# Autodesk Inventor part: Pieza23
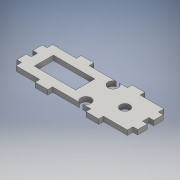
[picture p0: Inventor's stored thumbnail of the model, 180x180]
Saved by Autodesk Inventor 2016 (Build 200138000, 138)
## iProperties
Created: 2016-06
Part Number: Pieza23
Material: Genérico
Document SubType Name: Modeling
Designer: adm
Density: 1 g/cm^3
Appearance: Valor por defecto
Author: adm
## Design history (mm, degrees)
sketch "Boceto1"
  geometry: L1 (-15, -11.5)-(-15, -14.5); L2 (-23, -11.5)-(-23, -14.5); L3 (-23, -14.5)-(-15, -14.5); L4 (-15, -11.5)-(-23, -11.5); L5 (-23, 11.5)-(-15, 11.5); L6 (-15, 14.5)-(-23, 14.5); L7 (-15, 14.5)-(-15, 11.5); L8 (-40, -16.5)-(-40, 16.5); L9 (-35, -9.5)-(-35, -3.5); L10 (-35, 3.5)-(-35, 9.5); L11 (-23, 14.5)-(-23, 11.5); L12 (35, -3.5)-(35, -9.5); L13 (35, 9.5)-(35, 3.5); L14 (35, -9.5)-(38, -9.5); L15 (38, -9.5)-(38, -3.5); L16 (35, -3.5)-(38, -3.5); L17 (35, 9.5)-(38, 9.5); L18 (38, 3.5)-(38, 9.5); L19 (35, 3.5)-(38, 3.5); L20 (-38, 9.5)-(-35, 9.5); L21 (-38, 9.5)-(-38, 3.5); L22 (-38, 3.5)-(-35, 3.5); L23 (-38, -3.5)-(-35, -3.5); L24 (-38, -3.5)-(-38, -9.5); L25 (-38, -9.5)-(-35, -9.5); L26 (35, -11.5)-(-35, 11.5); L27 (-35, -11.5)-(28.913, 9.5); L28 (-40, 16.5)-(40, 16.5); L29 (40, -16.5)-(-40, -16.5); L30 (15, -11.5)-(15, -14.5); L31 (15, 14.5)-(15, 11.5); L32 (15, 11.5)-(23, 11.5); L33 (23, 14.5)-(23, 11.5); L34 (23, 14.5)-(15, 14.5); L35 (23, -11.5)-(23, -14.5); L36 (15, -14.5)-(23, -14.5); L37 (40, 16.5)-(40, -16.5); L38 (23, -11.5)-(15, -11.5); L39 (-35, -11.5)-(35, -11.5); L40 (35, -11.5)-(35, 11.5); L41 (35, 11.5)-(-35, 11.5); L42 (-35, 11.5)-(-35, -11.5); L43 (-35, -11.5)-(35, 11.5); L44 (35, -11.5)-(-35, 11.5); 2 further points
  constraints: 88 end point, 20 parallel, 11 horizontal, 10 perpendicular, 8 vertical, 3 midpoint, 2 horizontal alignment, 1 point on line
  dimensions: "d0" = 70 distance of L26.start L27.start; "d1" = 6 distance of L10.start L10.end; "d2" = 7 distance between parallel lines of L28 L20; "d3" = 6 distance of L18.start L17.end; "d4" = 33 distance between parallel lines of L29 L28; "d5" = 7 distance between parallel lines of L22 L23; "d6" = 7 distance between parallel lines of L29 L25
extrude "Extrusión1" new body sketch "Boceto1" distance "d7" = 3; taper "d8" = 0 deg
sketch "Boceto2"
  geometry: L1 (15, -11.5)-(23, -11.5); L2 (-3, -6)-(-3, 6); L3 (-15, -11.5)-(-15, -14.5); L4 (-29, -6)-(-3, -6); L5 (-29, 6)-(-29, -6); L6 (-3, 6)-(-29, 6); L7 (35, 3.5)-(35, 9.5); L8 (35, -3.5)-(35, -9.5); C1 r 3.175 at (6, -8.5); C2 r 3 at (22, 0); C3 r 3.175 at (6, 8.5); 3 further points
  constraints: 16 end point, 3 centre point, 2 parallel, 1 horizontal, 1 horizontal alignment, 1 midpoint, 1 perpendicular
  dimensions: "d10" = 6 diameter of C2; "d13" = 6.35 diameter of C3; "d14" = 6.35 diameter of C1; "d15" = 26 distance of L4.start L2.start; "d16" = 12 distance of L2.start L2.end; "d17" = 9 distance from line of C3.centre L2
extrude "Extrusión2" cut sketch "Boceto2" distance "d18" = 3; taper "d19" = 0 deg
sketch "Boceto3"
  geometry: L1 (35, 8)-(38, 8); L2 (38, 8)-(38, 2); L3 (38, 2)-(35, 2); L4 (35, 2)-(35, 8); L5 (35, -2)-(38, -2); L6 (38, -2)-(38, -8); L7 (38, -8)-(35, -8); L8 (35, -8)-(35, -2); L9 (7.04, -11.5)-(35, -11.5) reference; L10 (35, 11.5)-(7.04, 11.5) reference; L11 (0, 0)-(0, -19); L12 (-35, 8)-(-38, 8); L13 (-38, 8)-(-38, 2); L14 (-38, 2)-(-35, 2); L15 (-35, -2)-(-38, -2); L16 (-38, -2)-(-38, -8); L17 (-38, -8)-(-35, -8); L18 (-35, 8)-(-35, 2); L19 (-35, 11.5)-(-35, -11.5) reference; L20 (-35, -2)-(-35, -8)
  constraints: 34 end point, 8 symmetric about line, 4 parallel, 3 perpendicular, 2 horizontal, 2 vertical alignment, 1 collinear, 1 vertical
  dimensions: "d20" = 6 distance of L5.end L6.end; "d21" = 6 distance of L1.end L2.end; "d22" = 3 distance of L2.end L3.end; "d23" = 3 distance of L5.start L5.end; "d24" = 4 distance between parallel lines of L5 L3; "d25" = 3.5 distance between parallel lines of L9 L7; "d26" = 3.5 distance between parallel lines of L10 L1 (derived)
extrude "Extrusión3" join sketch "Boceto3" distance "d27" = 3; taper "d28" = 0 deg
sketch "Boceto4"
  geometry: L1 (7.04, -11.5)-(35, -11.5) reference; L2 (20, -11.5)-(12, -11.5); L3 (12, -11.5)-(12, -14.5); L4 (12, -14.5)-(20, -14.5); L5 (20, -14.5)-(20, -11.5); L6 (35, -11.5)-(35, -8) reference; L7 (0, 0)-(0, -20); L8 (0, 0)-(10, 0); L9 (-7.04, -11.5)-(-35, -11.5); L10 (-20, -11.5)-(-12, -11.5); L11 (-12, -11.5)-(-12, -14.5); L12 (-12, -14.5)-(-20, -14.5); L13 (-20, -14.5)-(-20, -11.5); L14 (7.04, 11.5)-(35, 11.5); L15 (20, 11.5)-(12, 11.5); L16 (12, 11.5)-(12, 14.5); L17 (12, 14.5)-(20, 14.5); L18 (20, 14.5)-(20, 11.5); L19 (0, 0)-(0, 20); L20 (-7.04, 11.5)-(-35, 11.5); L21 (-20, 11.5)-(-12, 11.5); L22 (-12, 11.5)-(-12, 14.5); L23 (-12, 14.5)-(-20, 14.5); L24 (-20, 14.5)-(-20, 11.5)
  constraints: 44 end point, 19 symmetric about line, 4 point on line, 2 parallel, 1 horizontal, 1 perpendicular, 1 vertical
  dimensions: "d29" = 8 distance of L3.end L4.end; "d30" = 15 distance between parallel lines of L6 L5; "d31" = 3 distance of L2.end L3.end
extrude "Extrusión4" join sketch "Boceto4" distance "d32" = 3; taper "d33" = 0 deg
node "Sólido1"
